// TIA Portal project "Zweipunk" (V14)

(* hardware
DEVICE "SIMATIC 300"  S7-300 station
   slot 0: "Rack 0"  Rail  6ES7 390-1***0-0AA0
   slot 2: "CPU 314C-2 DP"  CPU 314C-2 PN/DP  6ES7 314-6EH04-0AB0  V3.3
      slot 2: "PROFINET-Schnittstelle_1"  PN-IO
         slot 1: "Port_1"  Port
         slot 2: "Port_2"  Port
      slot 5: "DI 24/DO 16_1"  DI24/DO16
      slot 6: "AI 5/AO 2_1"  AI5/AO2
      slot 7: "Zählen_1"  Counter
      slot 8: "Positionieren_1"  Positioning
*)

// ===== PLC "CPU 314C-2 DP"  CPU 314C-2 PN/DP =====

VAR_GLOBAL   // PLC tag table "Standard-Variablentabelle"
   "AI1" AT %EW800 : Int;
   "AI2" AT %EW802 : Int;
   "Hysterese" AT %MW10 : Int;
   "immer low" AT %M0.0 : Bool;   // immer low
   "immer high" AT %M0.1 : Bool;   // immer high
   "Takt 2s (0,5Hz)" AT %M100.7 : Bool;   // Takt 2s (0,5Hz)
   "Takt 1s (1Hz)" AT %M100.5 : Bool;   // Takt 1s (1Hz)
   "Takt 1,6s (0,625Hz)" AT %M100.6 : Bool;   // Takt 1,6s (0,625Hz)
   "Takt 0,8s (1,25Hz)" AT %M100.4 : Bool;   // Takt 0,8s (1,25Hz)
   "Takt 0,5s (2Hz)" AT %M100.3 : Bool;   // Takt 0,5s (2Hz)
   "Takt 0,4s (2,5Hz)" AT %M100.2 : Bool;   // Takt 0,4s (2,5Hz)
   "Takt 0,2s (5Hz)" AT %M100.1 : Bool;   // Takt 0,2s (5Hz)
   "Takt 0,1s (10Hz)" AT %M100.0 : Bool;   // Takt 0,1s (10Hz)
   "Heizung EIN_AUS" AT %E0.0 : Bool;   // Heizung EIN_AUS
   "Heizen" AT %A4.0 : Bool;   // Heizen
   "HM Heizung EIN" AT %M0.2 : Bool;
END_VAR

DATA_BLOCK "Datenbaustein_1"   // DB1
{ S7_Optimized_Access := 'FALSE' }
VERSION : 0.1
   VAR
      Sollwert : Real;
      Istwert : Real;
      Hysterese : Real;
   END_VAR
BEGIN
END_DATA_BLOCK

FUNCTION "FC1" : Void   // FC1, FBD
TITLE = Parametrierung
{ S7_Optimized_Access := 'FALSE' }
VERSION : 0.1
   VAR_TEMP
      Temp_1 : Word;
   END_VAR
BEGIN

REGION Network 1: Einesle des Istwertes
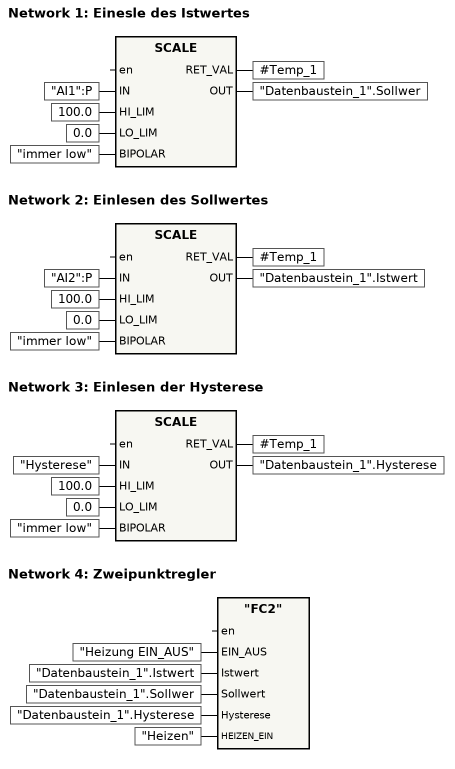
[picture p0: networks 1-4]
   #Temp_1 := SCALE(IN := "AI1":P,
                    HI_LIM := 100.0,
                    LO_LIM := 0.0,
                    BIPOLAR := "immer low",
                    OUT => "Datenbaustein_1".Sollwer);
END_REGION

REGION Network 2: Einlesen des Sollwertes
   #Temp_1 := SCALE(IN := "AI2":P,
                    HI_LIM := 100.0,
                    LO_LIM := 0.0,
                    BIPOLAR := "immer low",
                    OUT => "Datenbaustein_1".Istwert);
END_REGION

REGION Network 3: Einlesen der Hysterese
   #Temp_1 := SCALE(IN := "Hysterese",
                    HI_LIM := 100.0,
                    LO_LIM := 0.0,
                    BIPOLAR := "immer low",
                    OUT => "Datenbaustein_1".Hysterese);
END_REGION

REGION Network 4: Zweipunktregler
   "FC2"(EIN_AUS := "Heizung EIN_AUS",
         Istwert := "Datenbaustein_1".Istwert,
         Sollwert := "Datenbaustein_1".Sollwer,
         Hysterese := "Datenbaustein_1".Hysterese,
         HEIZEN_EIN := "Heizen");
END_REGION
END_FUNCTION

FUNCTION "FC2" : Void   // FC2, FBD
{ S7_Optimized_Access := 'FALSE' }
VERSION : 0.1
   VAR_INPUT
      EIN_AUS : Bool;
      Istwert : Real;
      Sollwert : Real;
      Hysterese : Real;
   END_VAR
   VAR_IN_OUT
      HEIZEN_EIN : Bool;
   END_VAR
   VAR_TEMP
      Schaltschwelle : Real;
   END_VAR
BEGIN

REGION Network 1: Heizung EIN AUS
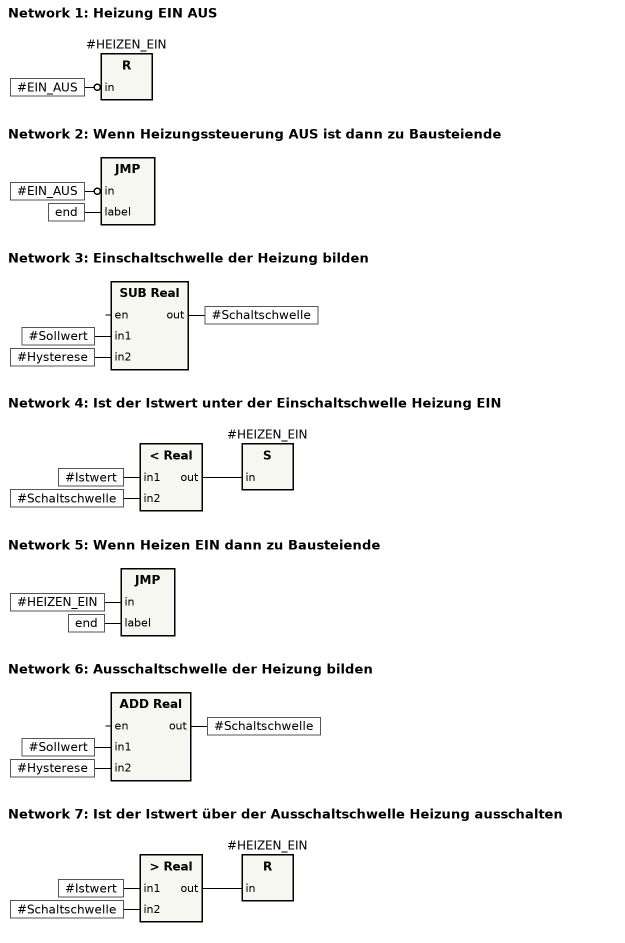
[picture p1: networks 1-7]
   IF NOT #EIN_AUS THEN #HEIZEN_EIN := FALSE; END_IF;
END_REGION

REGION Network 2: Wenn Heizungssteuerung AUS ist dann zu Bausteiende
   IF NOT #EIN_AUS THEN GOTO end; END_IF;
END_REGION

REGION Network 3: Einschaltschwelle der Heizung bilden
   #Schaltschwelle := #Sollwert - #Hysterese;
END_REGION

REGION Network 4: Ist der Istwert unter der Einschaltschwelle Heizung EIN
   IF #Istwert < #Schaltschwelle THEN #HEIZEN_EIN := TRUE; END_IF;
END_REGION

REGION Network 5: Wenn Heizen EIN dann zu Bausteiende
   IF #HEIZEN_EIN THEN GOTO end; END_IF;
END_REGION

REGION Network 6: Ausschaltschwelle der Heizung bilden
   #Schaltschwelle := #Sollwert + #Hysterese;
END_REGION

REGION Network 7: Ist der Istwert über der Ausschaltschwelle Heizung ausschalten
   IF #Istwert > #Schaltschwelle THEN #HEIZEN_EIN := FALSE; END_IF;
END_REGION

REGION Network 8 (STL): Bausteinende
   end:  NOP   0;
END_REGION
END_FUNCTION

ORGANIZATION_BLOCK "OB1"   // OB1, FBD
TITLE = "Main Program Sweep (Cycle)"
{ S7_Optimized_Access := 'FALSE' }
NAME : Kleissle
VERSION : 0.1
   VAR_TEMP
      OB1_EV_CLASS : Byte;   // Bits 0-3 = 1 (Coming event), Bits 4-7 = 1 (Event class 1)
      OB1_SCAN_1 : Byte;   // 1 (Cold restart scan 1 of OB 1), 3 (Scan 2-n of OB 1)
      OB1_PRIORITY : Byte;   // Priority of OB Execution
      OB1_OB_NUMBR : Byte;   // 1 (Organization block 1, OB1)
      OB1_RESERVED_1 : Byte;   // Reserved for system
      OB1_RESERVED_2 : Byte;   // Reserved for system
      OB1_PREV_CYCLE : Int;   // Cycle time of previous OB1 scan (milliseconds)
      OB1_MIN_CYCLE : Int;   // Minimum cycle time of OB1 (milliseconds)
      OB1_MAX_CYCLE : Int;   // Maximum cycle time of OB1 (milliseconds)
      OB1_DATE_TIME : Date_And_Time;   // Date and time OB1 started
   END_VAR
BEGIN

REGION Network 1 (STL): immer low
         CLR;
         =     "immer low";
         SET;
         =     "immer high";
END_REGION

REGION Network 2: Programmaufruf
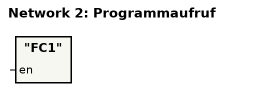
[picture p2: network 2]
   "FC1"();
END_REGION
END_ORGANIZATION_BLOCK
